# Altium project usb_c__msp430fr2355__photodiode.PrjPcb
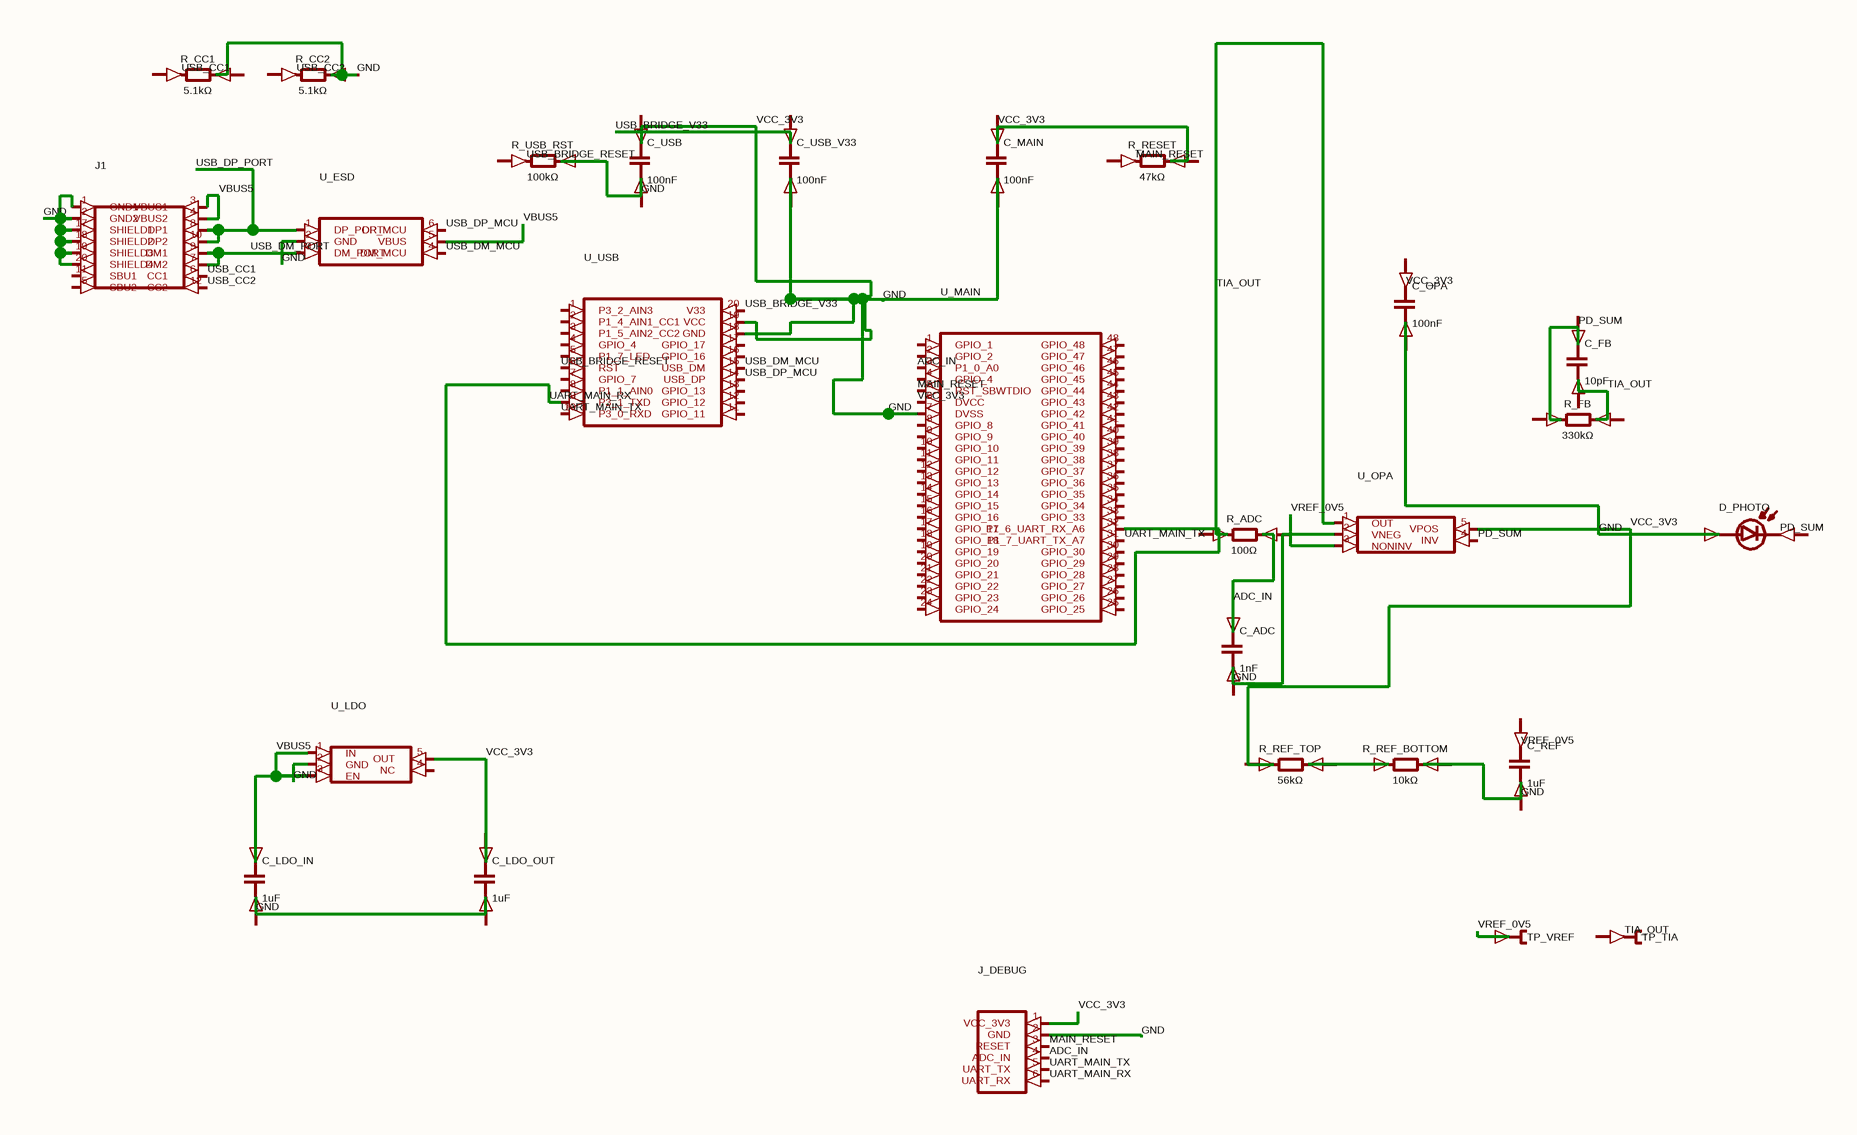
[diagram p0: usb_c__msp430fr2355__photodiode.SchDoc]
1 sheet, 27 parts. Net scope: global (net labels, ports and power ports of the same name join across sheets).
Board file: usb_c__msp430fr2355__photodiode.PcbDoc

## Sheet usb_c__msp430fr2355__photodiode.SchDoc
size 206 x 142 mm

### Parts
C_ADC  1nF
C_FB  10pF
C_LDO_IN  1uF
C_LDO_OUT  1uF
C_MAIN  100nF
C_OPA  100nF
C_REF  1uF
C_USB  100nF
C_USB_V33  100nF
D_PHOTO  (no value)
J1  (no value)
J_DEBUG  (no value)
R_ADC  100Ω
R_CC1  5.1kΩ
R_CC2  5.1kΩ
R_FB  330kΩ
R_REF_BOTTOM  10kΩ
R_REF_TOP  56kΩ
R_RESET  47kΩ
R_USB_RST  100kΩ
TP_TIA  (no value)
TP_VREF  (no value)
U_ESD  (no value)
U_LDO  (no value)
U_MAIN  (no value)
U_OPA  (no value)
U_USB  (no value)

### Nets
ADC_IN: C_ADC.1(anode) J_DEBUG.4(ADC_IN) U_MAIN.3(P1_0_A0)
GND: C_LDO_IN.1(anode) C_LDO_OUT.1(anode) C_MAIN.2(cathode) C_OPA.2(cathode) C_USB_V33.2(cathode) D_PHOTO.1(anode) J1.1(GND1) J1.2(GND2) J1.3(VBUS1) J1.4(VBUS2) J1.7(DM2) J1.9(DM1) J1.17(SHIELD1) J1.18(SHIELD2) J1.19(SHIELD3) J1.20(SHIELD4) J_DEBUG.1(VCC_3V3) J_DEBUG.2(GND) R_ADC.2(cathode) R_REF_BOTTOM.2(cathode) R_USB_RST.2(cathode) TP_VREF.1(pin1) U_ESD.2(GND) U_ESD.3(DM_PORT) U_ESD.5(VBUS) U_LDO.1(IN) U_LDO.2(GND) U_LDO.3(EN) U_LDO.5(OUT) U_MAIN.6(DVCC) U_MAIN.7(DVSS) U_OPA.2(VNEG) U_OPA.3(NONINV) U_OPA.5(VPOS) U_USB.18(GND) U_USB.19(VCC) U_USB.20(V33)  [also labelled USB_BRIDGE_V33, USB_DM_PORT, VBUS5, VCC_3V3, VREF_0V5]
MAIN_RESET: J_DEBUG.3(RESET) U_MAIN.5(RST_SBWTDIO)
PD_SUM: U_OPA.4(INV)
TIA_OUT: J_DEBUG.6(UART_RX) U_MAIN.32(P1_6_UART_RX_A6) U_OPA.1(OUT) U_USB.9(P3_1_TXD)  [also labelled UART_MAIN_RX]
UART_MAIN_TX: J_DEBUG.5(UART_TX) U_MAIN.31(P1_7_UART_TX_A7) U_USB.10(P3_0_RXD)
USB_BRIDGE_RESET: U_USB.6(RST)
USB_CC1: J1.6(CC1)
USB_CC2: J1.12(CC2)
USB_DM_MCU: U_ESD.4(DM_MCU) U_USB.15(USB_DM)
USB_DP_MCU: U_ESD.6(DP_MCU) U_USB.14(USB_DP)
USB_DP_PORT: J1.8(DP1) J1.10(DP2) U_ESD.1(DP_PORT)
NetR_REF_BOTTOM_1: R_REF_BOTTOM.1(anode) R_REF_TOP.2(cathode)

Not connected (* = marked no-connect by the designer): C_ADC 2(cathode); C_FB 1(anode) 2(cathode); C_LDO_IN 2(cathode); C_LDO_OUT 2(cathode); C_MAIN 1(anode); C_OPA 1(anode); C_REF 1(anode) 2(cathode); C_USB 1(anode) 2(cathode); C_USB_V33 1(anode); D_PHOTO 2(cathode); J1 5(SBU2) 11(SBU1); R_ADC 1(anode); R_CC1 1(anode) 2(cathode); R_CC2 1(anode) 2(cathode); R_FB 1(anode) 2(cathode); R_REF_TOP 1(anode); R_RESET 1(anode) 2(cathode); R_USB_RST 1(anode); TP_TIA 1(pin1); U_LDO 4(NC); U_MAIN 1(GPIO_1) 2(GPIO_2) 4(GPIO_4) 8(GPIO_8) 9(GPIO_9) 10(GPIO_10) 11(GPIO_11) 12(GPIO_12) 13(GPIO_13) 14(GPIO_14) 15(GPIO_15) 16(GPIO_16) 17(GPIO_17) 18(GPIO_18) 19(GPIO_19) 20(GPIO_20) 21(GPIO_21) 22(GPIO_22) 23(GPIO_23) 24(GPIO_24) 25(GPIO_25) 26(GPIO_26) 27(GPIO_27) 28(GPIO_28) 29(GPIO_29) 30(GPIO_30) 33(GPIO_33) 34(GPIO_34) 35(GPIO_35) 36(GPIO_36) 37(GPIO_37) 38(GPIO_38) 39(GPIO_39) 40(GPIO_40) 41(GPIO_41) 42(GPIO_42) 43(GPIO_43) 44(GPIO_44) 45(GPIO_45) 46(GPIO_46) 47(GPIO_47) 48(GPIO_48); U_USB 1(P3_2_AIN3) 2(P1_4_AIN1_CC1) 3(P1_5_AIN2_CC2) 4(GPIO_4) 5(P1_7_LED) 7(GPIO_7) 8(P1_1_AIN0) 11(GPIO_11) 12(GPIO_12) 13(GPIO_13) 16(GPIO_16) 17(GPIO_17)

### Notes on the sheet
- Labels drawn without touching a wire or pin: MAIN_RESET, PD_SUM, TIA_OUT, USB_BRIDGE_RESET, USB_CC1, USB_CC2, VCC_3V3, VREF_0V5

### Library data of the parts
C_ADC C_FB C_LDO_IN C_LDO_OUT C_MAIN C_OPA C_REF C_USB C_USB_V33 = capacitor_down
D_PHOTO = photodiode_horz
J1 = J1
J_DEBUG = J_DEBUG
R_ADC R_CC1 R_CC2 R_FB R_REF_BOTTOM R_REF_TOP R_RESET R_USB_RST = boxresistor_right
TP_TIA TP_VREF = testpoint_right
U_ESD = U_ESD
U_LDO = U_LDO
U_MAIN = U_MAIN
U_OPA = U_OPA
U_USB = U_USB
